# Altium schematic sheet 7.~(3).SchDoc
size 420 x 297 mm
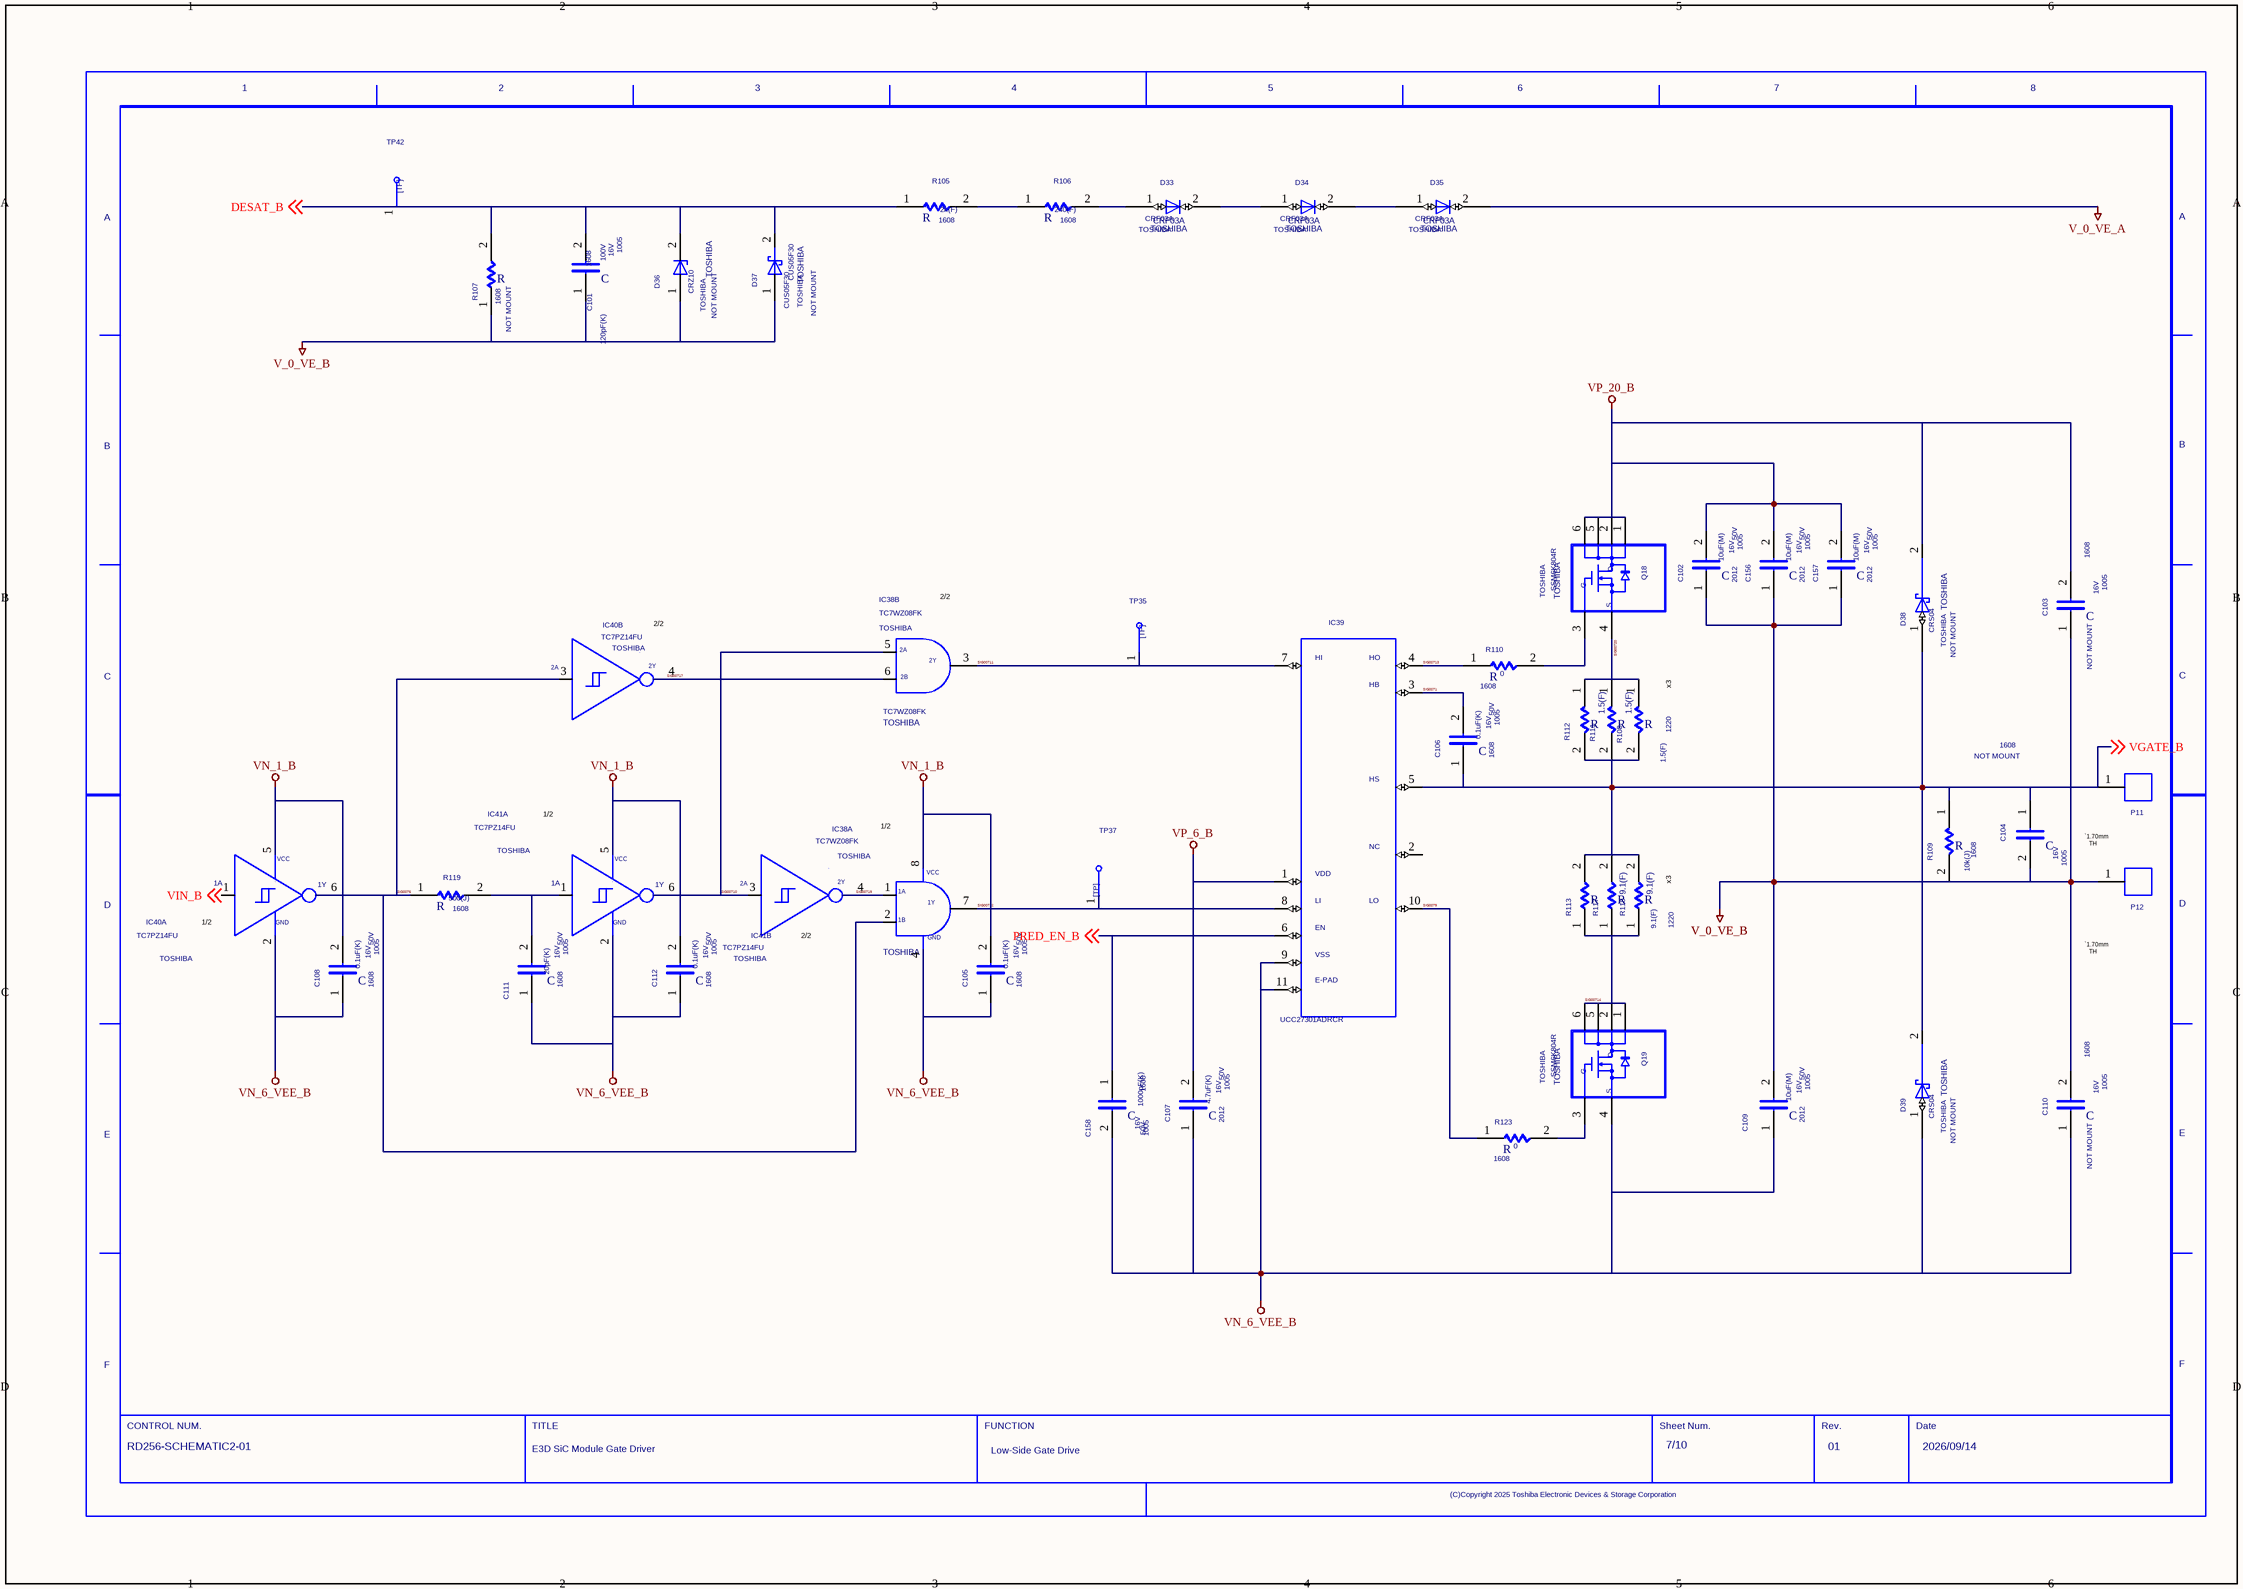
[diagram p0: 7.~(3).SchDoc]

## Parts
C101  VOLTAGE: 16V  CODE: 1005  VAL1: 120pF(K)  VAL2: 100V  SIZECODESMD: 1608  (hidden comment: C)
C102  VOLTAGE: 16V  CODE: 1005  VAL1: 10uF(M)  VAL2: 50V  SIZECODESMD: 2012  (hidden comment: C)
C103  VOLTAGE: 16V  CODE: 1005  SIZECODESMD: 1608  NOTMOUNT: NOT MOUNT  (hidden comment: C)
C104  VOLTAGE: 16V  CODE: 1005  SIZECODESMD: 1608  NOTMOUNT: NOT MOUNT  (hidden comment: C)
C105  VOLTAGE: 16V  CODE: 1005  VAL1: 0.1uF(K)  VAL2: 50V  SIZECODESMD: 1608  (hidden comment: C)
C106  VOLTAGE: 16V  CODE: 1005  VAL1: 0.1uF(K)  VAL2: 50V  SIZECODESMD: 1608  (hidden comment: C)
C107  VOLTAGE: 16V  CODE: 1005  VAL1: 4.7uF(K)  VAL2: 50V  SIZECODESMD: 2012  (hidden comment: C)
C108  VOLTAGE: 16V  CODE: 1005  VAL1: 0.1uF(K)  VAL2: 50V  SIZECODESMD: 1608  (hidden comment: C)
C109  VOLTAGE: 16V  CODE: 1005  VAL1: 10uF(M)  VAL2: 50V  SIZECODESMD: 2012  (hidden comment: C)
C110  VOLTAGE: 16V  CODE: 1005  SIZECODESMD: 1608  NOTMOUNT: NOT MOUNT  (hidden comment: C)
C111  VOLTAGE: 16V  CODE: 1005  VAL1: 20pF(K)  VAL2: 50V  SIZECODESMD: 1608  (hidden comment: C)
C112  VOLTAGE: 16V  CODE: 1005  VAL1: 0.1uF(K)  VAL2: 50V  SIZECODESMD: 1608  (hidden comment: C)
C156  VOLTAGE: 16V  CODE: 1005  VAL1: 10uF(M)  VAL2: 50V  SIZECODESMD: 2012  (hidden comment: C)
C157  VOLTAGE: 16V  CODE: 1005  VAL1: 10uF(M)  VAL2: 50V  SIZECODESMD: 2012  (hidden comment: C)
C158  VOLTAGE: 16V  CODE: 1005  VAL1: 1000pF(K)  VAL2: 50V  SIZECODESMD: 1608  (hidden comment: C)
D33  VENDOR: TOSHIBA  (hidden comment: CRF03A)
D34  VENDOR: TOSHIBA  (hidden comment: CRF03A)
D35  VENDOR: TOSHIBA  (hidden comment: CRF03A)
D36  VENDOR: TOSHIBA  NOTMOUNT: NOT MOUNT  (hidden comment: CRZ10)
D37  VENDOR: TOSHIBA  NOTMOUNT: NOT MOUNT  (hidden comment: CUS05F30)
D38  VENDOR: TOSHIBA  NOTMOUNT: NOT MOUNT  (hidden comment: CRS04)
D39  VENDOR: TOSHIBA  NOTMOUNT: NOT MOUNT  (hidden comment: CRS04)
IC38  VENDOR: TOSHIBA  (hidden comment: TC7WZ08FK)  (parts A,B of 2)
IC39  VAL3: UCC27301ADRCR  (hidden comment: UCC27301A)
IC40  VAL3: TC7PZ14FU  USERCOMPTEXT3: TOSHIBA  (hidden comment: TC7PZ17FU)  (parts A,B of 2)
IC41  VAL3: TC7PZ14FU  USERCOMPTEXT3: TOSHIBA  (hidden comment: TC7PZ17FU)  (parts A,B of 2)
P11  TH  (value not drawn)
P12  TH  (value not drawn)
Q18  VENDOR: TOSHIBA  (hidden comment: SSM6K804R)
Q19  VENDOR: TOSHIBA  (hidden comment: SSM6K804R)
R105  VAL1: 2k(F)  SIZECODESMD: 1608  (hidden comment: R)
R106  VAL1: 240(F)  SIZECODESMD: 1608  (hidden comment: R)
R107  SIZECODESMD: 1608  NOTMOUNT: NOT MOUNT  (hidden comment: R)
R108  VAL1: 1.5(F)  (hidden comment: R)
R109  VAL1: 10k(J)  SIZECODESMD: 1608  (hidden comment: R)
R110  VAL1: 0  SIZECODESMD: 1608  (hidden comment: R)
R111  VAL1: 1.5(F)  (hidden comment: R)
R112  VAL1: 1.5(F)  SIZECODESMD: 1220  (hidden comment: R)
R113  VAL1: 9.1(F)  SIZECODESMD: 1220  (hidden comment: R)
R117  VAL1: 9.1(F)  (hidden comment: R)
R118  VAL1: 9.1(F)  (hidden comment: R)
R119  VAL1: 500(J)  SIZECODESMD: 1608  (hidden comment: R)
R123  VAL1: 0  SIZECODESMD: 1608  (hidden comment: R)
TP35  TP  (value not drawn)
TP37  TP  (value not drawn)
TP42  TP  (value not drawn)
U?  REVISION: 01  SHEETNUMBER: 7/10  FUNCTION: Low-Side Gate Drive  TITLE: E3D SiC Module Gate Driver  DRAWINGNUMBER: RD256-SCHEMATIC2-01  DATE: 2026/09/14  (hidden comment: WAKU_DEF100)

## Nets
V_0_VE_A: D35.2(C)
V_0_VE_B: C101.1 C102.1 C103.1 C104.2 C109.2 C110.2 C156.1 C157.1 D36.1(A) D37.1(A) P12.1 R107.1 R109.2
VN_1_B: C105.2 C108.2 C112.2 IC38.8 IC40.5 IC41.5
VN_6_VEE_B: C105.1 C107.1 C108.1 C109.1 C110.1 C111.1 C112.1 C158.2 D39.1(A) IC38.4 IC39.9 IC39.11 IC40.2 IC41.2 Q19.4
VP_6_B: C107.2 IC39.1
VP_20_B: C102.2 C103.2 C156.2 C157.2 D38.2(C) Q18.1 Q18.2 Q18.5 Q18.6
DESAT_B: C101.2 D36.2(C) D37.2(C) R105.1 R107.2 TP42.1 ; off-sheet DESAT_B
PRED_EN_B: C158.1 IC39.6 ; off-sheet PRED_EN_B
SIG0071: C106.2 IC39.3
SIG0072: D33.2(C) D34.1(A)
SIG0073: D33.1(A) R106.2
SIG0075: Q18.3 R110.2
SIG0076: IC38.2 IC40.3 IC40.6 R119.1
SIG0077: D34.2(C) D35.1(A)
SIG0078: R105.2 R106.1
SIG0079: IC39.10 R123.1
SIG00710: IC38.5 IC41.3 IC41.6
SIG00711: IC38.3 IC39.7 TP35.1
SIG00712: IC38.7 IC39.8 TP37.1
SIG00713: IC39.4 R110.1
SIG00714: Q19.1 Q19.2 Q19.5 Q19.6 R113.1 R117.1 R118.1
SIG00716: C111.2 IC41.1 R119.2
SIG00717: IC38.6 IC40.4
SIG00718: Q19.3 R123.2
SIG00719: IC38.1 IC41.4
SIG00720: Q18.4 R108.1 R111.1 R112.1
VGATE_B: C104.1 C106.1 D38.1(A) D39.2(C) IC39.5 P11.1 R108.2 R109.1 R111.2 R112.2 R113.2 R117.2 R118.2 ; off-sheet VGATE_B
VIN_B: IC40.1 ; off-sheet VIN_B

Not connected (* = marked no-connect by the designer): IC39 2

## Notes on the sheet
- (near IC38) 2/2
- (near IC40) 2/2
- (near R108) x3
- (near IC41) 1/2
- (near IC38) 1/2
- `1.70mm
  TH
- (near IC40) 1/2
- (near IC41) 2/2
- (near R118) x3

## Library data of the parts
C101 C102 C105-C109 C111 C112 C156-C158 = C: ORIGINALSYMBOLORIGIN: (0,0); VC2: 0; PSPICETEMPLATE: C^@REFDES %1 %2 ?TOLERANCE¦C^@REFDES¦ @VALUE ?IC/IC=@IC/ TC=@TC1,@TC2 ?TOLERANCE¦\n.model C^@REFDES CAP C=1 DEV=@TOLERANCE% TC1=@TC1 TC2=@TC2 VC1=@VC1 VC2=@VC2¦; SAVECOUNT: 2; UPDATETIME: 08:48:12; UPDATEUSER: HP_Z8_KEYSHOT; INSTANCENAME: INS2265204
C103 C104 C110 = C: ORIGINALSYMBOLORIGIN: (0,0); VC2: 0; PSPICETEMPLATE: C^@REFDES %1 %2 ?TOLERANCE¦C^@REFDES¦ @VALUE ?IC/IC=@IC/ TC=@TC1,@TC2 ?TOLERANCE¦\n.model C^@REFDES CAP C=1 DEV=@TOLERANCE% TC1=@TC1 TC2=@TC2 VC1=@VC1 VC2=@VC2¦; SAVECOUNT: 2; UPDATETIME: 08:48:12; UPDATEUSER: HP_Z8_KEYSHOT; INSTANCENAME: INS2266227
D33-D35 = CRF03A: OriginalSymbolOrigin: (0,0); PSPICETEMPLATE: X^@REFDES %A %C @MODEL; SAVECOUNT: 2; UPDATETIME: 08:48:14; UPDATEUSER: HP_Z8_KEYSHOT; INSTANCENAME: INS2254974
D36 = CRZ10: ORIGINALSYMBOLORIGIN: (0,0); PSPICETEMPLATE: X^@REFDES %A %C @MODEL; SAVEAREA0: -4630,-153,17114,13055; SAVECOUNT: 6; UPDATETIME: 08:18:42; UPDATEUSER: fukuda-y; TIME: 14:49:55; INSTANCENAME: INS2255026
D37 = CUS05F30: ORIGINALSYMBOLORIGIN: (0,0); PSPICETEMPLATE: X^@REFDES %A %C @MODEL; SAVEAREA0: -4630,-153,17114,13055; SAVECOUNT: 9; UPDATETIME: 08:16:22; UPDATEUSER: fukuda-y; TIME: 14:49:55; INSTANCENAME: INS2255944
D38 D39 = CRS04: OriginalSymbolOrigin: (0,0); PSPICETEMPLATE: X^@REFDES %A %C @MODEL; SAVECOUNT: 2; UPDATETIME: 08:48:14; UPDATEUSER: HP_Z8_KEYSHOT; INSTANCENAME: INS2256112
IC38 = TC7WZ08FK_1: PART NUMBER: TC7W00FK; ORIGINALSYMBOLORIGIN: (2540,-2540); DESCRIPTION-A: NAND 2ch Logic; PSPICETEMPLATE: X^@REFDES %1A %1B %2Y %GND %2A %2B %1Y %VCC @MODEL; ・: 7 V; SPLIT_INST: TRUE; ORDER: $pOrder; SWAP_INFO: (S1+S2); SAVECOUNT: 9; UPDATETIME: 16:09:46; UPDATEUSER: sptcae09; TIME: 08:52:39; INSTANCENAME: INS2255192; CaptureCellPackProp: TC7WZ08FK_1A
IC39 = UCC27301A: OriginalSymbolOrigin: (5080,60960); PSPICETEMPLATE: X^@REFDES %VDD %NC %HB %HO %HS %EN %HI %LI %VSS %LO %THERMAL_PAD @MODEL; SAVECOUNT: 11; UPDATETIME: 20:55:41; UPDATEUSER: t5459927; TIME: 08:48:14
IC40 IC41 = TC7PZ14FU_2: OriginalSymbolOrigin: (5080,15240); SWAP_INFO: (S1+S2); PSPICETEMPLATE: X^@REFDES %1A %GND %2A %2Y %VCC %1Y @MODEL; SPLIT_INST: TRUE; SAVECOUNT: 4; UPDATETIME: 19:09:34; UPDATEUSER: t5459927; TIME: 11:55:01; INSTANCENAME: INS2255542; FUNCN: TC7PZ14FU_1; CaptureCellPackProp: TC7PZ14FU_2A
P11 = TH: ORIGINALSYMBOLORIGIN: (0,0); PSPICETEMPLATE: X^@REFDES %1 @MODEL; SAVECOUNT: 1; UPDATETIME: 18:11:32; UPDATEUSER: w20165dm; INSTANCENAME: INS2255180
P12 = TH: ORIGINALSYMBOLORIGIN: (0,0); PSPICETEMPLATE: X^@REFDES %1 @MODEL; SAVECOUNT: 1; UPDATETIME: 18:11:32; UPDATEUSER: w20165dm; INSTANCENAME: INS2256066
Q18 Q19 = SSM6K804R: PSPICETEMPLATE: X^@REFDES %1 %2 %3 %4 %5 %6 @MODEL; ORIGINALSYMBOLORIGIN: (0,0); SAVEAREA0: -7120,-295,29516,23636; SAVECOUNT: 14; UPDATETIME: 08:48:15; UPDATEUSER: HP_Z8_KEYSHOT; INSTANCENAME: INS2255292
R105 R106 R119 = R: ORIGINALSYMBOLORIGIN: (0,0); PSPICETEMPLATE: R^@REFDES %1 %2 ?TOLERANCE¦R^@REFDES¦ @VALUE TC=@TC1,@TC2 ?TOLERANCE¦\n.model R^@REFDES RES R=1 DEV=@TOLERANCE% TC1=@TC1 TC2=@TC2¦; TC2: 0; VAL2: 100mW; SAVECOUNT: 2; UPDATETIME: 08:48:13; UPDATEUSER: HP_Z8_KEYSHOT; INSTANCENAME: INS2263832
R107 = R: ORIGINALSYMBOLORIGIN: (0,0); PSPICETEMPLATE: R^@REFDES %1 %2 ?TOLERANCE¦R^@REFDES¦ @VALUE TC=@TC1,@TC2 ?TOLERANCE¦\n.model R^@REFDES RES R=1 DEV=@TOLERANCE% TC1=@TC1 TC2=@TC2¦; TC2: 0; VAL2: 0.125; SAVECOUNT: 2; UPDATETIME: 08:48:13; UPDATEUSER: HP_Z8_KEYSHOT; INSTANCENAME: INS2263832
R108 R111 R117 R118 = R: ORIGINALSYMBOLORIGIN: (0,0); PSPICETEMPLATE: R^@REFDES %1 %2 ?TOLERANCE¦R^@REFDES¦ @VALUE TC=@TC1,@TC2 ?TOLERANCE¦\n.model R^@REFDES RES R=1 DEV=@TOLERANCE% TC1=@TC1 TC2=@TC2¦; TC2: 0; VAL2: 1W; SAVECOUNT: 2; UPDATETIME: 08:48:13; UPDATEUSER: HP_Z8_KEYSHOT; INSTANCENAME: INS2256002; SIZECODESMD: 1220
R109 = R: ORIGINALSYMBOLORIGIN: (0,0); PSPICETEMPLATE: R^@REFDES %1 %2 ?TOLERANCE¦R^@REFDES¦ @VALUE TC=@TC1,@TC2 ?TOLERANCE¦\n.model R^@REFDES RES R=1 DEV=@TOLERANCE% TC1=@TC1 TC2=@TC2¦; TC2: 0; VAL2: 100mW; SAVECOUNT: 2; UPDATETIME: 08:48:13; UPDATEUSER: HP_Z8_KEYSHOT; INSTANCENAME: INS2266059
R110 R123 = R: ORIGINALSYMBOLORIGIN: (0,0); PSPICETEMPLATE: R^@REFDES %1 %2 ?TOLERANCE¦R^@REFDES¦ @VALUE TC=@TC1,@TC2 ?TOLERANCE¦\n.model R^@REFDES RES R=1 DEV=@TOLERANCE% TC1=@TC1 TC2=@TC2¦; VAL2: 0.125; SAVECOUNT: 2; UPDATETIME: 08:48:13; UPDATEUSER: HP_Z8_KEYSHOT; INSTANCENAME: INS2256002
R112 R113 = R: ORIGINALSYMBOLORIGIN: (0,0); PSPICETEMPLATE: R^@REFDES %1 %2 ?TOLERANCE¦R^@REFDES¦ @VALUE TC=@TC1,@TC2 ?TOLERANCE¦\n.model R^@REFDES RES R=1 DEV=@TOLERANCE% TC1=@TC1 TC2=@TC2¦; TC2: 0; VAL2: 1W; SAVECOUNT: 2; UPDATETIME: 08:48:13; UPDATEUSER: HP_Z8_KEYSHOT; INSTANCENAME: INS2256002
TP35 = TP: ORIGINALSYMBOLORIGIN: (0,0); SAVEAREA0: -242,-92,12810,7836; SAVECOUNT: 2; UPDATETIME: 16:18:11; UPDATEUSER: fukuda-y; TIME: 16:12:21; INSTANCENAME: INS2255892
TP37 = TP: ORIGINALSYMBOLORIGIN: (0,0); SAVEAREA0: -242,-92,12810,7836; SAVECOUNT: 2; UPDATETIME: 16:18:11; UPDATEUSER: fukuda-y; TIME: 16:12:21; INSTANCENAME: INS2255530
TP42 = TP: ORIGINALSYMBOLORIGIN: (0,0); SAVEAREA0: -242,-92,12810,7836; SAVECOUNT: 2; UPDATETIME: 16:18:11; UPDATEUSER: fukuda-y; TIME: 16:12:21; INSTANCENAME: INS2255794
U? = WAKU_DEF100: OriginalSymbolOrigin: (10160,284480); SAVECOUNT: 4; UPDATETIME: 12:22:01; UPDATEUSER: t5459927; TIME: 14:30:25; SAVEAREA0: -63393,-16950,474261,314592; PLOTTIME: HH:MM; SHTSAVECOUNT: 30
